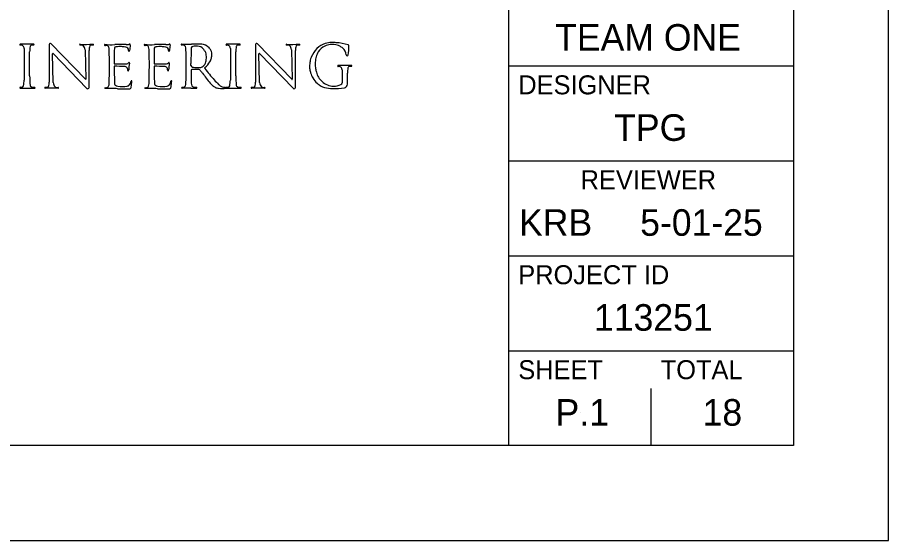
# Model space of a CAD drawing. Extents: x 0 to 34, y 0 to 22.
# Drawn here: x 29.412 to 34, y 0 to 2.755 of the extents above; entities that cross this region are included whole.
import ezdxf

# ---------------------------------------------------------------- set-up
doc = ezdxf.new("R2010")
doc.units = 0
for name, color, linetype in [('Default', 7, 'Continuous'), ('SH_Border', 7, 'Continuous'), ('SH_Cut_Line', 7, 'Continuous'), ('SH_Data', 7, 'Continuous')]:
    doc.layers.add(name, color=color, linetype=linetype)

msp = doc.modelspace()

# ---------------------------------------------------------------- linework, layer by layer
at = {"layer": 'Default'}
for p, q in [((31.1717, 2.5019), (31.1012, 2.5019)), ((31.1217, 2.4791), (31.1217, 2.4103)), ((31.1507, 2.4036), (31.1507, 2.4619))]:
    msp.add_line(p, q, dxfattribs=at)
for centre, radius, start, end in [((31.0652, 2.5163), 0.1064, 107.613, 135.2994), ((31.067, 2.5106), 0.1123, 90.0889, 107.613), ((31.0674, 2.3114), 0.3116, 85.6243, 90.0889), ((31.0684, 2.3246), 0.2983, 73.3259, 85.6243), ((31.0906, 2.4911), 0.1421, 135.2994, 157.2066), ((31.0704, 2.5261), 0.0876, 147.5385, 165.5071), ((31.0704, 2.5261), 0.0876, 116.7026, 147.5385), ((31.0635, 2.5399), 0.0723, 93.5922, 116.7026), ((31.0722, 2.4012), 0.2112, 87.6816, 93.5922), ((31.0783, 2.5499), 0.0624, 59.809, 87.6816), ((31.0374, 2.4797), 0.1436, 52.0865, 59.809), ((31.0967, 2.5558), 0.0471, 2.9119, 52.0865), ((31.1522, 2.6045), 0.00606, 1.0594, 73.3259), ((30.9097, 2.6001), 0.2486, 350.1479, 1.0594), ((31.1232, 2.4938), 0.1726, 167.8164, 176.8679), ((31.0366, 2.5125), 0.084, 158.442, 167.8164), ((31.0906, 2.4911), 0.1421, 157.2066, 158.442), ((31.1549, 2.5061), 0.1744, 167.8795, 178.2857), ((31.1142, 2.5148), 0.1328, 165.5071, 167.8795), ((31.1492, 2.5585), 0.00548, 182.9119, 350.1479), ((31.0626, 2.4971), 0.1119, 176.8679, 187.4835), ((31.0477, 2.4951), 0.0968, 187.4835, 199.5864), ((31.1006, 2.5077), 0.1201, 178.2857, 190.5998), ((31.2658, 2.5386), 0.2882, 190.5998, 194.5022), ((31.1012, 2.4994), 0.00249, 90, 277.32), ((31.1038, 2.4791), 0.0179, 0, 97.32), ((31.3457, 2.4619), 0.195, 172.0456, 180), ((31.1597, 2.4879), 0.00718, 114.8736, 172.0456), ((31.1691, 2.4675), 0.0297, 95.8947, 114.8736), ((31.188, 2.2848), 0.2134, 94.3316, 95.8947), ((31.1717, 2.4997), 0.0022, 274.3316, 90), ((31.1304, 2.5246), 0.1846, 199.5864, 208.6065), ((31.056, 2.484), 0.0999, 208.6065, 229.3453), ((31.0839, 2.4916), 0.1003, 194.5022, 227.8932), ((31.0827, 2.5152), 0.141, 229.3453, 237.7571), ((31.0524, 2.4671), 0.0841, 237.7571, 254.2366), ((31.0787, 2.4859), 0.0926, 227.8932, 268.7516), ((31.0743, 2.5446), 0.1647, 254.2366, 269.1033), ((31.0787, 2.4853), 0.092, 268.7516, 293.6665), ((31.1115, 2.4103), 0.0102, 293.6665, 0), ((31.1311, 2.4036), 0.0196, 278.6618, 0), ((31.0776, 2.7547), 0.3748, 269.1033, 278.6618)]:
    msp.add_arc(centre, radius, start, end, dxfattribs=at)
at = {"layer": 'SH_Border'}
for p, q in [((32, 0.5), (32, 21.5)), ((32, 2.5), (33.5, 2.5)), ((32, 2), (33.5, 2)), ((32, 1.5), (33.5, 1.5)), ((32, 1), (33.5, 1))]:
    msp.add_line(p, q, dxfattribs=at)
msp.add_lwpolyline([(1.5, 21.5), (33.5, 21.5), (33.5, 0.5), (1.5, 0.5)], close=True, dxfattribs=at)
at = {"layer": 'SH_Cut_Line'}
msp.add_lwpolyline([(0, 0), (34, 0), (34, 22), (0, 22)], close=True, dxfattribs=at)
at = {"layer": 'SH_Data'}
for p, q in [((29.7707, 2.4292), (29.5903, 2.6167)), ((30.8574, 2.4292), (30.6771, 2.6167)), ((29.4979, 2.6141), (29.4273, 2.6141)), ((29.4478, 2.5914), (29.4478, 2.4255)), ((29.4768, 2.4472), (29.4768, 2.5741)), ((29.58, 2.6126), (29.58, 2.4147)), ((29.7688, 2.5843), (29.7722, 2.4298)), ((29.7896, 2.3858), (29.7896, 2.5815)), ((30.5837, 2.6141), (30.5131, 2.6141)), ((30.5336, 2.5914), (30.5336, 2.4255)), ((30.5626, 2.4472), (30.5626, 2.5741)), ((30.6667, 2.6126), (30.6667, 2.4147)), ((30.8556, 2.5843), (30.8589, 2.4298)), ((30.8764, 2.3858), (30.8764, 2.5815)), ((29.6008, 2.4119), (29.5975, 2.5631)), ((29.6004, 2.5643), (29.7787, 2.3814)), ((30.6875, 2.4119), (30.6842, 2.5631)), ((30.6872, 2.5643), (30.8655, 2.3814)), ((30.3263, 2.5024), (30.3263, 2.512)), ((30.3265, 2.4753), (30.3265, 2.4753)), ((29.4278, 2.3818), (29.503, 2.3818)), ((30.2794, 2.3826), (30.2794, 2.3826)), ((30.5136, 2.3818), (30.5888, 2.3818)), ((32.75, 0.5), (32.75, 0.8)), ((32.375, 0.675), (32.375, 0.675))]:
    msp.add_line(p, q, dxfattribs=at)
for centre, radius, start, end in [((29.586, 2.6126), 0.00603, 43.8796, 180), ((30.6727, 2.6126), 0.00603, 43.8796, 180), ((29.4273, 2.6116), 0.00249, 90, 277.32), ((29.4299, 2.5914), 0.0179, 0, 97.32), ((29.6718, 2.5741), 0.195, 172.0456, 180), ((29.4858, 2.6001), 0.00718, 114.8736, 172.0456), ((29.4953, 2.5797), 0.0297, 95.8947, 114.8736), ((29.5141, 2.397), 0.2134, 94.3316, 95.8947), ((29.4979, 2.6119), 0.0022, 274.3316, 90), ((29.7421, 2.6117), 0.00205, 88.0144, 271.2216), ((29.7709, 3.4445), 0.8313, 268.0144, 272.7235), ((29.7432, 2.5564), 0.0533, 76.384, 91.2216), ((29.7542, 2.6017), 0.00669, 47.2331, 76.384), ((29.7375, 2.5836), 0.0313, 1.2424, 47.2331), ((29.8515, 2.5815), 0.0619, 157.8419, 180), ((29.798, 2.6033), 0.00413, 102.9109, 157.8419), ((29.8097, 2.5525), 0.0562, 89.1136, 102.9109), ((29.8106, 2.6115), 0.00275, 269.1136, 92.7235), ((29.8724, 2.6103), 0.00228, 85.6429, 267.986), ((29.8761, 2.7147), 0.1067, 267.986, 269.6056), ((29.9057, 3.0477), 0.4363, 265.6429, 272.4818), ((29.8742, 2.4467), 0.1612, 87.8585, 89.6056), ((29.8794, 2.5861), 0.0217, 70.7604, 87.8585), ((29.8833, 2.597), 0.0102, 19.7623, 70.7604), ((29.8466, 2.5839), 0.0491, 1.7776, 19.7623), ((26.9395, 2.4993), 2.9574, 358.2224, 1.6678), ((33.7304, 2.5161), 3.8083, 178.862, 180.092), ((29.9319, 2.5916), 0.00901, 166.7992, 178.862), ((29.9319, 2.5916), 0.00901, 94.329, 166.7992), ((29.9691, 1.5854), 1.0273, 90.6415, 92.4818), ((29.9579, 2.2485), 0.353, 91.9186, 94.329), ((29.9514, 2.4429), 0.1586, 84.8974, 91.9186), ((29.962, 2.2196), 0.393, 86.7596, 90.6415), ((29.9214, 2.1077), 0.4951, 82.8496, 84.8974), ((29.9809, 2.5821), 0.0169, 354.4676, 82.8496), ((29.987, 2.6605), 0.0485, 266.7596, 287.419), ((30.0005, 2.5802), 0.00275, 174.4676, 355.814), ((30.0028, 2.6102), 0.00418, 350.1932, 107.419), ((30.3048, 2.558), 0.3024, 170.1932, 175.8069), ((30.0825, 2.6103), 0.00228, 85.6429, 267.986), ((30.0862, 2.7147), 0.1067, 267.986, 269.6056), ((30.1159, 3.0477), 0.4363, 265.6429, 272.4818), ((30.0844, 2.4467), 0.1612, 87.8585, 89.6056), ((30.0896, 2.5861), 0.0217, 70.7604, 87.8585), ((30.0934, 2.597), 0.0102, 19.7623, 70.7604), ((30.0567, 2.5839), 0.0491, 1.7776, 19.7623), ((27.1497, 2.4993), 2.9574, 358.2224, 1.6678), ((33.9405, 2.5161), 3.8083, 178.862, 180.092), ((30.142, 2.5916), 0.00901, 166.7992, 178.862), ((30.142, 2.5916), 0.00901, 94.329, 166.7992), ((30.1792, 1.5854), 1.0273, 90.6415, 92.4818), ((30.168, 2.2485), 0.353, 91.9186, 94.329), ((30.1615, 2.4429), 0.1586, 84.8974, 91.9186), ((30.1721, 2.2196), 0.393, 86.7596, 90.6415), ((30.1316, 2.1077), 0.4951, 82.8496, 84.8974), ((30.1911, 2.5821), 0.0169, 354.4676, 82.8496), ((30.1971, 2.6605), 0.0485, 266.7596, 287.419), ((30.2107, 2.5802), 0.00275, 174.4676, 355.814), ((30.2129, 2.6102), 0.00418, 350.1932, 107.419), ((30.515, 2.558), 0.3024, 170.1932, 175.8069), ((30.2766, 2.6123), 0.00228, 85.6429, 267.986), ((30.2802, 2.7167), 0.1067, 267.986, 269.6056), ((30.3099, 3.0496), 0.4363, 265.6429, 272.4818), ((30.2784, 2.4487), 0.1612, 87.8585, 89.6056), ((30.2836, 2.5881), 0.0217, 70.7604, 87.8585), ((30.2874, 2.599), 0.0102, 19.7623, 70.7604), ((30.2508, 2.5858), 0.0491, 1.7776, 19.7623), ((27.3437, 2.5013), 2.9574, 358.2224, 1.6678), ((34.1346, 2.5181), 3.8083, 178.862, 180.092), ((30.3361, 2.5936), 0.00901, 166.7992, 178.862), ((30.3361, 2.5936), 0.00901, 94.329, 166.7992), ((30.3733, 1.5874), 1.0273, 90.6415, 92.4818), ((30.362, 2.2505), 0.353, 91.9186, 94.329), ((30.3555, 2.4449), 0.1586, 87.9458, 91.9186), ((30.3597, 2.5621), 0.0413, 41.4498, 87.9458), ((30.3662, 2.2216), 0.393, 88.9596, 90.6415), ((30.3719, 2.5378), 0.0768, 59.0124, 88.9596), ((30.3063, 2.5149), 0.1125, 33.1566, 41.4498), ((30.3687, 2.5557), 0.038, 12.4025, 33.1566), ((30.3848, 2.5593), 0.0517, 36.4904, 59.0124), ((30.3859, 2.5601), 0.0504, 18.3247, 36.4904), ((30.386, 2.5601), 0.0503, 0.8515, 18.3247), ((30.5131, 2.6116), 0.00249, 90, 277.32), ((30.5157, 2.5914), 0.0179, 0, 97.32), ((30.7576, 2.5741), 0.195, 172.0456, 180), ((30.5716, 2.6001), 0.00718, 114.8736, 172.0456), ((30.5811, 2.5797), 0.0297, 95.8947, 114.8736), ((30.5999, 2.397), 0.2134, 94.3316, 95.8947), ((30.5837, 2.6119), 0.0022, 274.3316, 90), ((30.8288, 2.6117), 0.00205, 88.0144, 271.2216), ((30.8577, 3.4445), 0.8313, 268.0144, 272.7235), ((30.83, 2.5564), 0.0533, 76.384, 91.2216), ((30.841, 2.6017), 0.00669, 47.2331, 76.384), ((30.8242, 2.5836), 0.0313, 1.2424, 47.2331), ((30.9383, 2.5815), 0.0619, 157.8419, 180), ((30.8848, 2.6033), 0.00413, 102.9109, 157.8419), ((30.8964, 2.5525), 0.0562, 89.1136, 102.9109), ((30.8973, 2.6115), 0.00275, 269.1136, 92.7235), ((29.5992, 2.5632), 0.0017, 44.2691, 181.2424), ((30.3407, 2.5393), 0.0666, 344.0376, 355.1956), ((30.3316, 2.5475), 0.076, 0.6715, 12.4025), ((30.2537, 2.5466), 0.1539, 355.1956, 0.6715), ((30.3708, 2.5561), 0.0651, 328.0114, 346.8148), ((30.3555, 2.5597), 0.0808, 346.8148, 0.8515), ((30.6859, 2.5632), 0.0017, 44.2691, 181.2424), ((29.8209, 65.5698), 63.0599, 270.092005, 270.136322), ((33.7304, 2.5161), 3.8083, 180.2792, 181.6334), ((29.9267, 1.4406), 1.057, 87.1452, 90.2477), ((29.9706, 2.6539), 0.1438, 270.1363, 276.9085), ((29.9787, 2.4823), 0.014, 16.8614, 87.1452), ((29.9861, 2.526), 0.0149, 276.9085, 321.2725), ((29.9574, 2.4759), 0.0362, 359.2549, 16.8614), ((29.9821, 2.4801), 0.0163, 340.6106, 358.1882), ((29.9997, 2.5151), 0.0025, 349.4309, 141.2725), ((30.2288, 2.4723), 0.2305, 169.4309, 178.1882), ((30.031, 65.5698), 63.0599, 270.092005, 270.136322), ((33.9405, 2.5161), 3.8083, 180.2792, 181.6334), ((30.1369, 1.4406), 1.057, 87.1452, 90.2477), ((30.1807, 2.6539), 0.1438, 270.1363, 276.9085), ((30.1888, 2.4823), 0.014, 16.8614, 87.1452), ((30.1962, 2.526), 0.0149, 276.9085, 321.2725), ((30.1676, 2.4759), 0.0362, 359.2549, 16.8614), ((30.1922, 2.4801), 0.0163, 340.6106, 358.1882), ((30.2098, 2.5151), 0.0025, 349.4309, 141.2725), ((30.4389, 2.4723), 0.2305, 169.4309, 178.1882), ((30.3356, 2.5024), 0.00923, 180.1856, 255.4509), ((30.3317, 2.4753), 0.00518, 96.1813, 180.644), ((30.3343, 2.4512), 0.0294, 91.4758, 96.1813), ((30.3485, 2.5521), 0.0605, 255.4509, 268.1519), ((30.3445, 2.0567), 0.424, 86.8098, 91.4758), ((30.373, 3.3129), 0.8217, 268.1519, 269.8456), ((30.3675, 2.4701), 0.00998, 36.3661, 86.8098), ((30.3709, 2.5318), 0.0407, 269.8456, 280.9677), ((30.3739, 2.5164), 0.025, 280.9677, 313.7308), ((30.3569, 2.5342), 0.0495, 313.7308, 327.7207), ((30.4027, 2.4888), 0.00435, 129.1113, 218.1225), ((30.3555, 2.5351), 0.0512, 327.7207, 344.0376), ((31.5193, 3.365), 1.4237, 218.1225, 221.2578), ((30.3246, 2.5849), 0.1196, 309.1113, 328.0114), ((30.1206, 2.4472), 0.6438, 180, 184.4616), ((29.9956, 2.4754), 0.00196, 179.2549, 340.6106), ((30.2057, 2.4754), 0.00196, 179.2549, 340.6106), ((34.1346, 2.5181), 3.8083, 180.6446, 181.6334), ((31.0787, 2.9938), 0.8732, 216.3661, 217.5467), ((32.8858, 4.3828), 3.1524, 217.5467, 218.7682), ((31.2064, 2.4472), 0.6438, 180, 184.4616), ((29.4278, 2.3844), 0.00264, 91.3892, 270), ((29.4249, 2.5024), 0.1153, 271.3892, 275.8469), ((29.4357, 2.3966), 0.00897, 275.8469, 347.6428), ((29.3037, 2.4255), 0.1441, 347.6428, 360), ((29.4874, 2.3978), 0.00863, 184.4616, 238.9441), ((29.4919, 2.4053), 0.0174, 238.9441, 264.1674), ((29.5115, 2.5972), 0.2103, 264.1674, 267.7015), ((29.503, 2.3844), 0.00262, 270, 87.7015), ((29.559, 2.3847), 0.00275, 89.1136, 272.7235), ((29.5599, 2.4437), 0.0562, 269.1136, 282.9109), ((29.5716, 2.3929), 0.00413, 282.9109, 337.8419), ((29.518, 2.4147), 0.0619, 337.8419, 0), ((29.6321, 2.4125), 0.0313, 181.2424, 227.2331), ((29.6154, 2.3944), 0.00669, 227.2331, 256.384), ((29.6263, 2.4397), 0.0533, 256.384, 271.2216), ((29.6275, 2.3844), 0.00205, 268.0144, 91.2216), ((29.7713, 2.4298), 0.00087, 223.8796, 1.2424), ((29.7833, 2.3858), 0.00635, 224.2691, 0), ((29.8793, 2.4068), 0.0217, 272.1415, 289.2396), ((29.8831, 2.3959), 0.0102, 289.2396, 340.2377), ((29.8464, 2.4091), 0.0491, 340.2377, 358.2224), ((29.936, 2.4079), 0.0123, 181.6334, 198.7573), ((29.936, 2.4079), 0.0123, 198.7573, 233.0825), ((29.9449, 2.4199), 0.0272, 233.0825, 262.3896), ((29.9645, 2.5662), 0.1748, 262.3896, 278.3614), ((29.987, 2.4129), 0.0199, 278.3614, 320.8407), ((29.9722, 2.4249), 0.039, 320.8407, 340.269), ((29.9735, 2.4245), 0.0376, 340.269, 352.7536), ((29.9963, 2.3914), 0.0156, 326.4436, 352.6026), ((30.0129, 2.4195), 0.00209, 355.1286, 172.7536), ((29.3362, 2.4771), 0.6812, 352.6026, 355.1286), ((30.0894, 2.4068), 0.0217, 272.1415, 289.2396), ((30.0932, 2.3959), 0.0102, 289.2396, 340.2377), ((30.0566, 2.4091), 0.0491, 340.2377, 358.2224), ((30.1461, 2.4079), 0.0123, 181.6334, 198.7573), ((30.1461, 2.4079), 0.0123, 198.7573, 233.0825), ((30.1551, 2.4199), 0.0272, 233.0825, 262.3896), ((30.1746, 2.5662), 0.1748, 262.3896, 278.3614), ((30.1972, 2.4129), 0.0199, 278.3614, 320.8407), ((30.1823, 2.4249), 0.039, 320.8407, 340.269), ((30.1836, 2.4245), 0.0376, 340.269, 352.7536), ((30.2064, 2.3914), 0.0156, 326.4436, 352.6026), ((30.223, 2.4195), 0.00209, 355.1286, 172.7536), ((29.5463, 2.4771), 0.6812, 352.6026, 355.1286), ((30.2794, 2.3848), 0.00217, 90.3944, 271.2938), ((30.2782, 2.5482), 0.1612, 270.3944, 272.1415), ((30.2834, 2.4088), 0.0217, 272.1415, 289.2396), ((30.2872, 2.3979), 0.0102, 289.2396, 340.2377), ((30.2506, 2.4111), 0.0491, 340.2377, 358.2224), ((30.3662, 2.4106), 0.0384, 181.6334, 205.2525), ((30.3404, 2.3985), 0.00988, 205.2525, 258.54), ((30.3559, 2.4747), 0.0877, 258.54, 269.5198), ((30.3551, 2.3846), 0.00247, 269.9476, 89.5198), ((30.5058, 2.4714), 0.0998, 218.7682, 229.3302), ((30.484, 2.446), 0.0664, 229.3302, 242.6024), ((30.7983, 2.7325), 0.4645, 221.2578, 225.3035), ((30.4747, 2.428), 0.0462, 242.6024, 266.5374), ((30.5111, 2.4423), 0.0563, 225.3035, 240.2632), ((30.5062, 2.4336), 0.0463, 240.2632, 258.7004), ((30.5118, 2.4615), 0.0747, 258.7004, 268.9258), ((30.5103, 2.3842), 0.00255, 272.7345, 88.9258), ((30.5136, 2.3844), 0.00264, 91.3892, 270), ((30.5107, 2.5024), 0.1153, 271.3892, 275.8469), ((30.5215, 2.3966), 0.00897, 275.8469, 347.6428), ((30.3895, 2.4255), 0.1441, 347.6428, 360), ((30.5732, 2.3978), 0.00863, 184.4616, 238.9441), ((30.5777, 2.4053), 0.0174, 238.9441, 264.1674), ((30.5973, 2.5972), 0.2103, 264.1674, 267.7015), ((30.5888, 2.3844), 0.00262, 270, 87.7015), ((30.6458, 2.3847), 0.00275, 89.1136, 272.7235), ((30.6467, 2.4437), 0.0562, 269.1136, 282.9109), ((30.6583, 2.3929), 0.00413, 282.9109, 337.8419), ((30.6048, 2.4147), 0.0619, 337.8419, 0), ((30.7189, 2.4125), 0.0313, 181.2424, 227.2331), ((30.7021, 2.3944), 0.00669, 227.2331, 256.384), ((30.7131, 2.4397), 0.0533, 256.384, 271.2216), ((30.7143, 2.3844), 0.00205, 268.0144, 91.2216), ((30.8581, 2.4298), 0.00087, 223.8796, 1.2424), ((30.87, 2.3858), 0.00635, 224.2691, 0), ((29.5986, 1.5516), 0.8313, 88.0144, 92.7235), ((29.8752, 2.3828), 0.00217, 90.3944, 271.2943), ((29.8741, 2.5462), 0.1612, 270.3944, 272.1415), ((29.9008, 1.2492), 1.1317, 89.661, 91.2938), ((29.9048, 1.9197), 0.4612, 85.604, 89.661), ((29.9753, 2.8372), 0.4589, 265.604, 270.141), ((29.9757, 2.6585), 0.2803, 270.141, 275.8096), ((30.0034, 2.3867), 0.00707, 275.8096, 326.4436), ((30.0853, 2.3828), 0.00217, 90.3944, 271.2943), ((30.0842, 2.5462), 0.1612, 270.3944, 272.1415), ((30.1109, 1.2492), 1.1317, 89.661, 91.2938), ((30.1149, 1.9197), 0.4612, 85.604, 89.661), ((30.1854, 2.8372), 0.4589, 265.604, 270.141), ((30.1859, 2.6585), 0.2803, 270.141, 275.8096), ((30.2135, 2.3867), 0.00707, 275.8096, 326.4436), ((30.305, 1.2512), 1.1317, 89.661, 91.2938), ((30.3089, 1.9217), 0.4612, 88.0337, 89.661), ((30.356, 3.2922), 0.9101, 268.0337, 269.9476), ((30.4934, 2.738), 0.3567, 266.5374, 272.7345), ((30.6854, 1.5516), 0.8313, 88.0144, 92.7235)]:
    msp.add_arc(centre, radius, start, end, dxfattribs=at)

# ---------------------------------------------------------------- texts
for s, height, p in [('TEAM ONE', 0.14, (32.2444, 2.58)), ('DESIGNER', 0.1, (32.05, 2.35)), ('TPG', 0.14, (32.555, 2.105)), ('REVIEWER', 0.1, (32.3783, 1.85)), ('KRB', 0.14, (32.0541, 1.605)), ('5-01-25', 0.14, (32.692, 1.605)), ('PROJECT ID', 0.1, (32.05, 1.35)), ('113251', 0.14, (32.449, 1.105)), ('SHEET', 0.1, (32.05, 0.85)), ('TOTAL', 0.1, (32.8, 0.85)), ('P.1', 0.14, (32.2462, 0.605)), ('18', 0.14, (33.0206, 0.605))]:
    msp.add_text(s, height=height, dxfattribs=at).set_placement(p)

doc.saveas('drawing.dxf')
